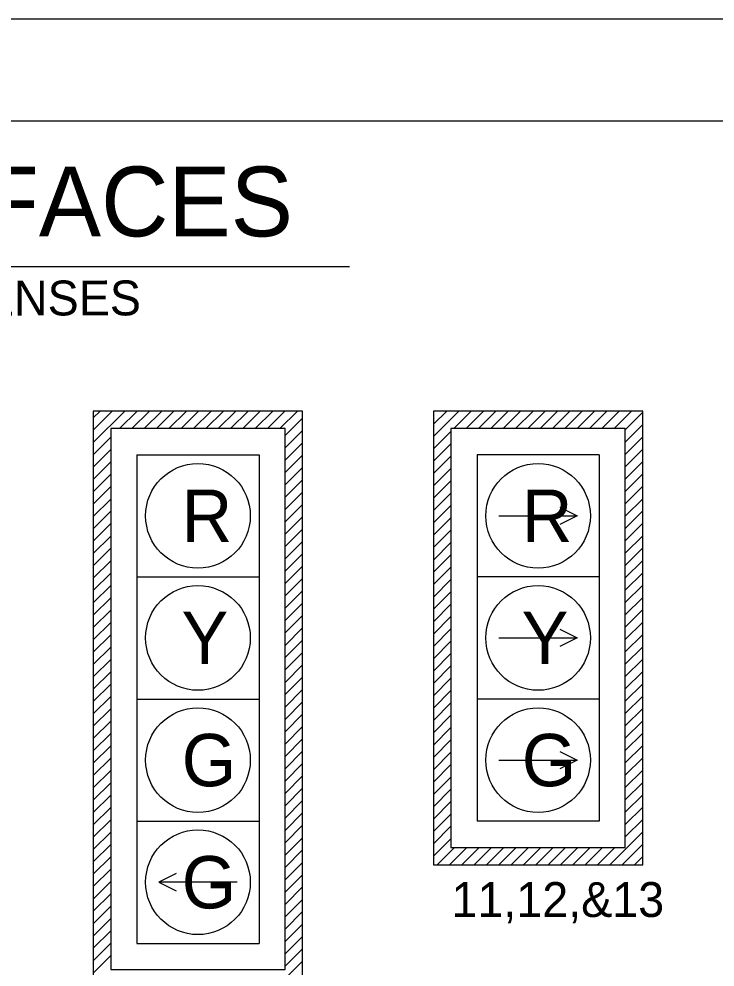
# Model space of a CAD drawing. Extents: x 660063 to 664816, y 641756 to 643817.
# Drawn here: x 661694.2 to 661774.1, y 642780 to 642888.7 of the extents above; entities that cross this region are included whole.
import ezdxf

# ---------------------------------------------------------------- set-up
doc = ezdxf.new("R2010")
doc.units = 0
for name, color, linetype in [('Default', 7, 'Continuous'), ('R_Border', 7, 'Continuous'), ('R_No Plot', 7, 'Continuous'), ('T_Drafting', 7, 'Continuous'), ('T_Notes', 7, 'Continuous')]:
    doc.layers.add(name, color=color, linetype=linetype)

msp = doc.modelspace()

# ---------------------------------------------------------------- linework, layer by layer
at = {"layer": 'R_Border'}
msp.add_line((661447.99, 642876.97), (662396.53, 642876.97), dxfattribs=at)
at = {"layer": 'R_No Plot'}
msp.add_line((661410.79, 642888.66), (662410.79, 642888.66), dxfattribs=at)
msp.add_lwpolyline([(661410.77, 642888.66), (662410.79, 642888.66), (662410.79, 642248.64), (661410.77, 642248.64)], close=True, dxfattribs=at)
at = {"layer": 'T_Drafting'}
for p, q in [((661726.76, 642843.72), (661702.76, 642843.72)), ((661702.76, 642843.72), (661702.76, 642777.72)), ((661702.76, 642840.13), (661706.36, 642843.72)), ((661702.76, 642841.54), (661704.94, 642843.72)), ((661702.76, 642842.96), (661703.53, 642843.72)), ((661705.77, 642841.72), (661707.77, 642843.72)), ((661707.19, 642841.72), (661709.19, 642843.72)), ((661708.6, 642841.72), (661710.6, 642843.72)), ((661710.01, 642841.72), (661712.01, 642843.72)), ((661711.43, 642841.72), (661713.43, 642843.72)), ((661712.84, 642841.72), (661714.84, 642843.72)), ((661714.26, 642841.72), (661716.26, 642843.72)), ((661715.67, 642841.72), (661717.67, 642843.72)), ((661717.09, 642841.72), (661719.09, 642843.72)), ((661718.5, 642841.72), (661720.5, 642843.72)), ((661719.91, 642841.72), (661721.91, 642843.72)), ((661721.33, 642841.72), (661723.33, 642843.72)), ((661722.74, 642841.72), (661724.74, 642843.72)), ((661724.16, 642841.72), (661726.16, 642843.72)), ((661726.76, 642777.72), (661726.76, 642843.72)), ((661765.76, 642843.72), (661741.76, 642843.72)), ((661741.76, 642843.72), (661741.76, 642791.72)), ((661741.76, 642840.8), (661744.69, 642843.72)), ((661741.76, 642842.21), (661743.28, 642843.72)), ((661741.76, 642843.62), (661741.86, 642843.72)), ((661744.1, 642841.72), (661746.1, 642843.72)), ((661745.52, 642841.72), (661747.52, 642843.72)), ((661746.93, 642841.72), (661748.93, 642843.72)), ((661748.35, 642841.72), (661750.35, 642843.72)), ((661749.76, 642841.72), (661751.76, 642843.72)), ((661751.18, 642841.72), (661753.18, 642843.72)), ((661752.59, 642841.72), (661754.59, 642843.72)), ((661754, 642841.72), (661756, 642843.72)), ((661755.42, 642841.72), (661757.42, 642843.72)), ((661756.83, 642841.72), (661758.83, 642843.72)), ((661758.25, 642841.72), (661760.25, 642843.72)), ((661759.66, 642841.72), (661761.66, 642843.72)), ((661761.07, 642841.72), (661763.07, 642843.72)), ((661762.49, 642841.72), (661764.49, 642843.72)), ((661763.76, 642841.58), (661765.76, 642843.58)), ((661765.76, 642791.72), (661765.76, 642843.72)), ((661724.76, 642840.92), (661726.76, 642842.92)), ((661763.76, 642840.17), (661765.76, 642842.17)), ((661724.76, 642839.5), (661726.76, 642841.5)), ((661741.76, 642839.38), (661743.76, 642841.38)), ((661702.76, 642838.71), (661704.76, 642840.71)), ((661724.76, 642838.09), (661726.76, 642840.09)), ((661763.76, 642838.75), (661765.76, 642840.75)), ((661702.76, 642837.3), (661704.76, 642839.3)), ((661741.76, 642837.97), (661743.76, 642839.97)), ((661763.76, 642837.34), (661765.76, 642839.34)), ((661702.76, 642835.89), (661704.76, 642837.89)), ((661707.76, 642838.72), (661721.76, 642838.72)), ((661707.76, 642838.72), (661707.76, 642824.72)), ((661721.76, 642838.72), (661721.76, 642824.72)), ((661724.76, 642836.67), (661726.76, 642838.67)), ((661741.76, 642836.55), (661743.76, 642838.55)), ((661760.76, 642838.72), (661746.76, 642838.72)), ((661746.76, 642838.72), (661746.76, 642824.72)), ((661760.76, 642838.72), (661760.76, 642824.72)), ((661763.76, 642835.93), (661765.76, 642837.93)), ((661724.76, 642835.26), (661726.76, 642837.26)), ((661741.76, 642835.14), (661743.76, 642837.14)), ((661702.76, 642834.47), (661704.76, 642836.47)), ((661724.76, 642833.84), (661726.76, 642835.84)), ((661741.76, 642833.73), (661743.76, 642835.73)), ((661763.76, 642834.51), (661765.76, 642836.51)), ((661702.76, 642833.06), (661704.76, 642835.06)), ((661763.76, 642833.1), (661765.76, 642835.1)), ((661702.76, 642831.64), (661704.76, 642833.64)), ((661724.76, 642832.43), (661726.76, 642834.43)), ((661741.76, 642832.31), (661743.76, 642834.31)), ((661763.76, 642831.68), (661765.76, 642833.68)), ((661724.76, 642831.02), (661726.76, 642833.02)), ((661741.76, 642830.9), (661743.76, 642832.9)), ((661702.76, 642830.23), (661704.76, 642832.23)), ((661724.76, 642829.6), (661726.76, 642831.6)), ((661741.76, 642829.48), (661743.76, 642831.48)), ((661749.26, 642831.72), (661758.26, 642831.72)), ((661763.76, 642830.27), (661765.76, 642832.27)), ((661702.76, 642828.82), (661704.76, 642830.82)), ((661763.76, 642828.86), (661765.76, 642830.86)), ((661702.76, 642827.4), (661704.76, 642829.4)), ((661724.76, 642828.19), (661726.76, 642830.19)), ((661741.76, 642828.07), (661743.76, 642830.07)), ((661763.76, 642827.44), (661765.76, 642829.44)), ((661724.76, 642826.77), (661726.76, 642828.77)), ((661741.76, 642826.65), (661743.76, 642828.65)), ((661763.76, 642826.03), (661765.76, 642828.03)), ((661702.76, 642825.99), (661704.76, 642827.99)), ((661724.76, 642825.36), (661726.76, 642827.36)), ((661741.76, 642825.24), (661743.76, 642827.24)), ((661702.76, 642824.57), (661704.76, 642826.57)), ((661724.76, 642823.95), (661726.76, 642825.95)), ((661763.76, 642824.61), (661765.76, 642826.61)), ((661702.76, 642823.16), (661704.76, 642825.16)), ((661741.76, 642823.83), (661743.76, 642825.83)), ((661763.76, 642823.2), (661765.76, 642825.2)), ((661702.76, 642821.74), (661704.76, 642823.74)), ((661707.76, 642824.72), (661721.76, 642824.72)), ((661707.76, 642824.72), (661707.76, 642810.72)), ((661721.76, 642824.72), (661721.76, 642810.72)), ((661724.76, 642822.53), (661726.76, 642824.53)), ((661741.76, 642822.41), (661743.76, 642824.41)), ((661760.76, 642824.72), (661746.76, 642824.72)), ((661746.76, 642824.72), (661746.76, 642810.72)), ((661760.76, 642824.72), (661760.76, 642810.72)), ((661763.76, 642821.78), (661765.76, 642823.78)), ((661724.76, 642821.12), (661726.76, 642823.12)), ((661741.76, 642821), (661743.76, 642823)), ((661702.76, 642820.33), (661704.76, 642822.33)), ((661724.76, 642819.7), (661726.76, 642821.7)), ((661741.76, 642819.58), (661743.76, 642821.58)), ((661763.76, 642820.37), (661765.76, 642822.37)), ((661702.76, 642818.92), (661704.76, 642820.92)), ((661763.76, 642818.96), (661765.76, 642820.96)), ((661702.76, 642817.5), (661704.76, 642819.5)), ((661724.76, 642818.29), (661726.76, 642820.29)), ((661741.76, 642818.17), (661743.76, 642820.17)), ((661763.76, 642817.54), (661765.76, 642819.54)), ((661724.76, 642816.87), (661726.76, 642818.87)), ((661741.76, 642816.75), (661743.76, 642818.75)), ((661702.76, 642816.09), (661704.76, 642818.09)), ((661724.76, 642815.46), (661726.76, 642817.46)), ((661741.76, 642815.34), (661743.76, 642817.34)), ((661749.26, 642817.72), (661758.26, 642817.72)), ((661763.76, 642816.13), (661765.76, 642818.13)), ((661702.76, 642814.67), (661704.76, 642816.67)), ((661763.76, 642814.71), (661765.76, 642816.71)), ((661702.76, 642813.26), (661704.76, 642815.26)), ((661724.76, 642814.05), (661726.76, 642816.05)), ((661741.76, 642813.93), (661743.76, 642815.93)), ((661763.76, 642813.3), (661765.76, 642815.3)), ((661724.76, 642812.63), (661726.76, 642814.63)), ((661741.76, 642812.51), (661743.76, 642814.51)), ((661702.76, 642811.84), (661704.76, 642813.84)), ((661724.76, 642811.22), (661726.76, 642813.22)), ((661741.76, 642811.1), (661743.76, 642813.1)), ((661763.76, 642811.88), (661765.76, 642813.88)), ((661702.76, 642810.43), (661704.76, 642812.43)), ((661724.76, 642809.8), (661726.76, 642811.8)), ((661763.76, 642810.47), (661765.76, 642812.47)), ((661702.76, 642809.02), (661704.76, 642811.02)), ((661707.76, 642810.72), (661721.76, 642810.72)), ((661707.76, 642810.72), (661707.76, 642796.72)), ((661721.76, 642810.72), (661721.76, 642796.72)), ((661741.76, 642809.68), (661743.76, 642811.68)), ((661760.76, 642810.72), (661746.76, 642810.72)), ((661746.76, 642810.72), (661746.76, 642796.72)), ((661760.76, 642810.72), (661760.76, 642796.72)), ((661763.76, 642809.06), (661765.76, 642811.06)), ((661702.76, 642807.6), (661704.76, 642809.6)), ((661724.76, 642808.39), (661726.76, 642810.39)), ((661741.76, 642808.27), (661743.76, 642810.27)), ((661763.76, 642807.64), (661765.76, 642809.64)), ((661724.76, 642806.97), (661726.76, 642808.97)), ((661741.76, 642806.86), (661743.76, 642808.86)), ((661702.76, 642806.19), (661704.76, 642808.19)), ((661724.76, 642805.56), (661726.76, 642807.56)), ((661741.76, 642805.44), (661743.76, 642807.44)), ((661763.76, 642806.23), (661765.76, 642808.23)), ((661702.76, 642804.77), (661704.76, 642806.77)), ((661763.76, 642804.81), (661765.76, 642806.81)), ((661702.76, 642803.36), (661704.76, 642805.36)), ((661724.76, 642804.15), (661726.76, 642806.15)), ((661741.76, 642804.03), (661743.76, 642806.03)), ((661763.76, 642803.4), (661765.76, 642805.4)), ((661724.76, 642802.73), (661726.76, 642804.73)), ((661741.76, 642802.61), (661743.76, 642804.61)), ((661702.76, 642801.95), (661704.76, 642803.95)), ((661724.76, 642801.32), (661726.76, 642803.32)), ((661741.76, 642801.2), (661743.76, 642803.2)), ((661749.26, 642803.72), (661758.26, 642803.72)), ((661763.76, 642801.99), (661765.76, 642803.99)), ((661702.76, 642800.53), (661704.76, 642802.53)), ((661763.76, 642800.57), (661765.76, 642802.57)), ((661702.76, 642799.12), (661704.76, 642801.12)), ((661724.76, 642799.9), (661726.76, 642801.9)), ((661741.76, 642799.78), (661743.76, 642801.78)), ((661763.76, 642799.16), (661765.76, 642801.16)), ((661724.76, 642798.49), (661726.76, 642800.49)), ((661741.76, 642798.37), (661743.76, 642800.37)), ((661702.76, 642797.7), (661704.76, 642799.7)), ((661724.76, 642797.08), (661726.76, 642799.08)), ((661741.76, 642796.96), (661743.76, 642798.96)), ((661763.76, 642797.74), (661765.76, 642799.74)), ((661702.76, 642796.29), (661704.76, 642798.29)), ((661724.76, 642795.66), (661726.76, 642797.66)), ((661763.76, 642796.33), (661765.76, 642798.33)), ((661702.76, 642794.87), (661704.76, 642796.87)), ((661707.76, 642796.72), (661721.76, 642796.72)), ((661707.76, 642796.72), (661707.76, 642782.72)), ((661721.76, 642796.72), (661721.76, 642782.72)), ((661741.76, 642795.54), (661743.76, 642797.54)), ((661760.76, 642796.72), (661746.76, 642796.72)), ((661763.76, 642794.91), (661765.76, 642796.91)), ((661702.76, 642793.46), (661704.76, 642795.46)), ((661724.76, 642794.25), (661726.76, 642796.25)), ((661741.76, 642794.13), (661743.76, 642796.13)), ((661761.99, 642791.72), (661765.76, 642795.5)), ((661724.76, 642792.83), (661726.76, 642794.83)), ((661741.76, 642792.71), (661743.76, 642794.71)), ((661702.76, 642792.05), (661704.76, 642794.05)), ((661724.76, 642791.42), (661726.76, 642793.42)), ((661742.19, 642791.72), (661744.19, 642793.72)), ((661743.6, 642791.72), (661745.6, 642793.72)), ((661745.02, 642791.72), (661747.02, 642793.72)), ((661746.43, 642791.72), (661748.43, 642793.72)), ((661747.84, 642791.72), (661749.84, 642793.72)), ((661749.26, 642791.72), (661751.26, 642793.72)), ((661750.67, 642791.72), (661752.67, 642793.72)), ((661752.09, 642791.72), (661754.09, 642793.72)), ((661753.5, 642791.72), (661755.5, 642793.72)), ((661754.92, 642791.72), (661756.92, 642793.72)), ((661756.33, 642791.72), (661758.33, 642793.72)), ((661757.74, 642791.72), (661759.74, 642793.72)), ((661759.16, 642791.72), (661761.16, 642793.72)), ((661760.57, 642791.72), (661762.57, 642793.72)), ((661763.4, 642791.72), (661765.76, 642794.09)), ((661702.76, 642790.63), (661704.76, 642792.63)), ((661764.81, 642791.72), (661765.76, 642792.67)), ((661702.76, 642789.22), (661704.76, 642791.22)), ((661724.76, 642790), (661726.76, 642792)), ((661741.76, 642791.72), (661765.76, 642791.72)), ((661724.76, 642788.59), (661726.76, 642790.59)), ((661702.76, 642787.8), (661704.76, 642789.8)), ((661719.26, 642789.72), (661710.26, 642789.72)), ((661724.76, 642787.18), (661726.76, 642789.18)), ((661702.76, 642786.39), (661704.76, 642788.39)), ((661702.76, 642784.97), (661704.76, 642786.97)), ((661724.76, 642785.76), (661726.76, 642787.76)), ((661724.76, 642784.35), (661726.76, 642786.35)), ((661702.76, 642783.56), (661704.76, 642785.56)), ((661724.76, 642782.93), (661726.76, 642784.93)), ((661702.76, 642782.15), (661704.76, 642784.15)), ((661724.76, 642781.52), (661726.76, 642783.52)), ((661702.76, 642780.73), (661704.76, 642782.73)), ((661707.76, 642782.72), (661721.76, 642782.72)), ((661702.76, 642779.32), (661704.76, 642781.32)), ((661724.76, 642780.1), (661726.76, 642782.1)), ((661723.8, 642777.72), (661726.76, 642780.69))]:
    msp.add_line(p, q, dxfattribs=at)
for points in [[(661724.76, 642841.72), (661704.76, 642841.72), (661704.76, 642779.72), (661724.76, 642779.72)], [(661763.76, 642841.72), (661743.76, 642841.72), (661743.76, 642793.72), (661763.76, 642793.72)]]:
    msp.add_lwpolyline(points, close=True, dxfattribs=at)
for points in [[(661756.26, 642832.72), (661758.26, 642831.72), (661756.26, 642830.72)], [(661756.26, 642818.72), (661758.26, 642817.72), (661756.26, 642816.72)], [(661756.26, 642804.72), (661758.26, 642803.72), (661756.26, 642802.72)], [(661712.26, 642790.72), (661710.26, 642789.72), (661712.26, 642788.72)]]:
    msp.add_lwpolyline(points, dxfattribs=at)
for centre in [(661714.76, 642831.72), (661753.76, 642831.72), (661714.76, 642817.72), (661753.76, 642817.72), (661714.76, 642803.72), (661753.76, 642803.72), (661714.76, 642789.72)]:
    msp.add_circle(centre, 6, dxfattribs=at)
at = {"layer": 'T_Notes'}
msp.add_line((661646.17, 642860.27), (661732.14, 642860.27), dxfattribs=at)

# ---------------------------------------------------------------- texts
at = {"layer": 'Default'}
msp.add_text('11,12,&13', height=4, dxfattribs=at).set_placement((661743.83, 642785.74))
at = {"layer": 'T_Drafting'}
msp.add_text('12" LENSES', height=4, rotation=0.072, dxfattribs=at).set_placement((661677.78, 642854.65))
for s, p in [('R', (661712.9, 642828.72)), ('R', (661751.9, 642828.72)), ('Y', (661712.88, 642814.72)), ('Y', (661751.88, 642814.72)), ('G', (661712.9, 642800.72)), ('G', (661751.9, 642800.72)), ('G', (661712.9, 642786.72))]:
    msp.add_text(s, height=6, dxfattribs=at).set_placement(p)
at = {"layer": 'T_Notes'}
msp.add_text('SIGNAL FACES', height=8, dxfattribs=at).set_placement((661647.77, 642863.74))

doc.saveas('drawing.dxf')
